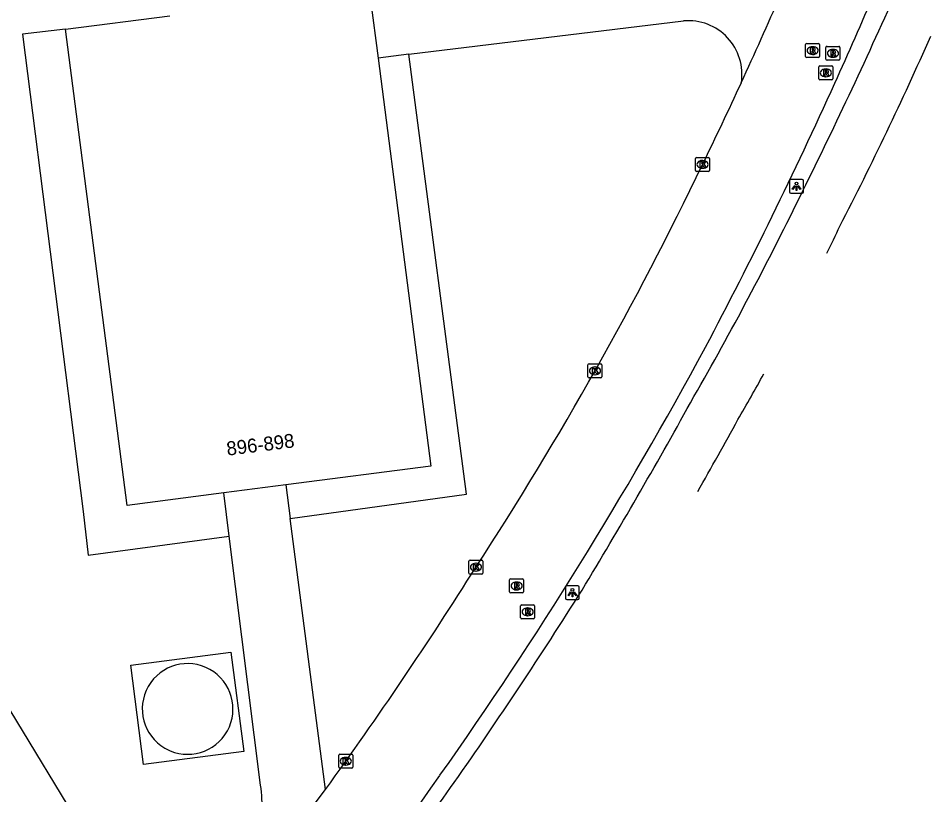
# Model space of a CAD drawing. Extents: x 154324 to 155743, y 382939 to 384183.
# Drawn here: x 155622.5 to 155688.2, y 383657.6 to 383713.4 of the extents above; entities that cross this region are included whole.
import ezdxf

# ---------------------------------------------------------------- set-up
doc = ezdxf.new("R2010")
doc.units = 0
for name, color, linetype in [('IMGEO_Fietspad_gesloten', 7, 'Continuous'), ('IMGEO_Kolk', 7, 'Continuous'), ('IMGEO_Lichtpunt', 7, 'Continuous'), ('IMGEO_Loofbos', 7, 'Continuous'), ('IMGEO_Opslagtank', 7, 'Continuous'), ('IMGEO_Pand', 7, 'Continuous'), ('IMGEO_Pand_nummerreeks', 7, 'Continuous'), ('IMGEO_Rijbaan_lokaal_gesloten', 7, 'Continuous'), ('IMGEO_Rijbaan_lokaal_open', 7, 'Continuous'), ('IMGEO_Rioolput', 7, 'Continuous'), ('IMGEO_Voetpad_gesloten', 7, 'Continuous'), ('IMGEO_Voetpad_open', 7, 'Continuous')]:
    doc.layers.add(name, color=color, linetype=linetype)

msp = doc.modelspace()

# ---------------------------------------------------------------- linework, layer by layer
at = {"layer": 'IMGEO_Fietspad_gesloten'}
for centre, radius, start, end in [((155322.907, 383877.011), 397.2, 333.53674, 335.8978), ((155458.585, 383813.415), 250.935, 332.72542, 336.18528), ((155452.6, 383811.231), 251.785, 330.10335, 333.78543), ((155506.608, 383781.846), 193.88, 333.87848, 334.51454), ((155506.608, 383781.846), 193.88, 329.86987, 330.98464), ((155318.174, 383880.881), 403.093, 328.83338, 331.04455), ((155440.078, 383812.046), 266.679, 330.15924, 331.43334), ((155375.44, 383853.45), 339.952, 324.99586, 327.79438), ((155331.975, 383886.464), 394.498, 322.54614, 324.68943)]:
    msp.add_arc(centre, radius, start, end, dxfattribs=at)
at = {"layer": 'IMGEO_Kolk'}
for p, q in [((155671.322, 383703.362), (155672.174, 383703.362)), ((155671.247, 383702.436), (155671.247, 383703.288)), ((155671.735, 383703.142), (155671.76, 383703.142)), ((155672.248, 383703.288), (155672.248, 383702.436)), ((155672.174, 383702.362), (155671.322, 383702.362)), ((155671.758, 383702.582), (155671.733, 383702.582)), ((155663.509, 383687.597), (155663.509, 383688.449)), ((155663.584, 383688.523), (155664.436, 383688.523)), ((155663.997, 383688.303), (155664.022, 383688.303)), ((155664.51, 383688.449), (155664.51, 383687.597)), ((155664.02, 383687.743), (155663.995, 383687.743)), ((155664.436, 383687.523), (155663.584, 383687.523)), ((155654.951, 383673.488), (155654.951, 383674.34)), ((155655.026, 383674.414), (155655.878, 383674.414)), ((155655.439, 383674.194), (155655.464, 383674.194)), ((155655.952, 383674.34), (155655.952, 383673.488)), ((155655.878, 383673.414), (155655.026, 383673.414)), ((155655.462, 383673.634), (155655.437, 383673.634)), ((155645.593, 383659.536), (155645.593, 383660.388)), ((155645.668, 383660.462), (155646.52, 383660.462)), ((155646.081, 383660.242), (155646.106, 383660.242)), ((155646.594, 383660.388), (155646.594, 383659.536)), ((155646.52, 383659.462), (155645.668, 383659.462)), ((155646.104, 383659.682), (155646.079, 383659.682))]:
    msp.add_line(p, q, dxfattribs=at)
for points in [[(155671.322, 383703.362), (155672.174, 383703.362)], [(155671.247, 383702.436), (155671.247, 383703.288)], [(155671.568, 383703.062), (155671.691, 383703.062), (155671.691, 383702.911), (155671.821, 383703.062), (155671.985, 383703.062), (155671.839, 383702.911), (155671.992, 383702.662), (155671.84, 383702.662), (155671.755, 383702.826), (155671.691, 383702.759), (155671.691, 383702.662), (155671.568, 383702.662), (155671.568, 383703.062)], [(155672.248, 383703.288), (155672.248, 383702.436)], [(155672.174, 383702.362), (155671.322, 383702.362)], [(155663.509, 383687.597), (155663.509, 383688.449)], [(155663.584, 383688.523), (155664.436, 383688.523)], [(155664.51, 383688.449), (155664.51, 383687.597)], [(155663.83, 383688.223), (155663.953, 383688.223), (155663.953, 383688.072), (155664.083, 383688.223), (155664.247, 383688.223), (155664.101, 383688.072), (155664.254, 383687.823), (155664.102, 383687.823), (155664.017, 383687.987), (155663.953, 383687.92), (155663.953, 383687.823), (155663.83, 383687.823), (155663.83, 383688.223)], [(155664.436, 383687.523), (155663.584, 383687.523)], [(155654.951, 383673.488), (155654.951, 383674.34)], [(155655.026, 383674.414), (155655.878, 383674.414)], [(155655.272, 383674.114), (155655.395, 383674.114), (155655.395, 383673.963), (155655.525, 383674.114), (155655.689, 383674.114), (155655.543, 383673.963), (155655.696, 383673.714), (155655.544, 383673.714), (155655.459, 383673.878), (155655.395, 383673.811), (155655.395, 383673.714), (155655.272, 383673.714), (155655.272, 383674.114)], [(155655.952, 383674.34), (155655.952, 383673.488)], [(155655.878, 383673.414), (155655.026, 383673.414)], [(155645.593, 383659.536), (155645.593, 383660.388)], [(155645.668, 383660.462), (155646.52, 383660.462)], [(155645.914, 383660.162), (155646.037, 383660.162), (155646.037, 383660.011), (155646.167, 383660.162), (155646.331, 383660.162), (155646.185, 383660.011), (155646.338, 383659.762), (155646.186, 383659.762), (155646.101, 383659.926), (155646.037, 383659.859), (155646.037, 383659.762), (155645.914, 383659.762), (155645.914, 383660.162)], [(155646.594, 383660.388), (155646.594, 383659.536)], [(155646.52, 383659.462), (155645.668, 383659.462)]]:
    msp.add_lwpolyline(points, dxfattribs=at)
for centre, start, end in [((155671.324, 383703.286), 91.55205, 178.44795), ((155671.324, 383703.286), 91.55205, 178.44795), ((155672.172, 383703.286), 1.55205, 88.44795), ((155672.172, 383703.286), 1.55205, 88.44795), ((155671.324, 383702.438), 181.55205, 268.44795), ((155671.324, 383702.438), 181.55205, 268.44795), ((155672.172, 383702.438), 271.55205, 358.44795), ((155672.172, 383702.438), 271.55205, 358.44795), ((155663.586, 383688.447), 91.55205, 178.44795), ((155663.586, 383688.447), 91.55205, 178.44795), ((155664.434, 383688.447), 1.55205, 88.44795), ((155664.434, 383688.447), 1.55205, 88.44795), ((155663.586, 383687.599), 181.55205, 268.44795), ((155663.586, 383687.599), 181.55205, 268.44795), ((155664.434, 383687.599), 271.55205, 358.44795), ((155664.434, 383687.599), 271.55205, 358.44795), ((155655.028, 383674.338), 91.55205, 178.44795), ((155655.028, 383674.338), 91.55205, 178.44795), ((155655.876, 383674.338), 1.55205, 88.44795), ((155655.876, 383674.338), 1.55205, 88.44795), ((155655.028, 383673.49), 181.55205, 268.44795), ((155655.028, 383673.49), 181.55205, 268.44795), ((155655.876, 383673.49), 271.55205, 358.44795), ((155655.876, 383673.49), 271.55205, 358.44795), ((155645.67, 383660.386), 91.55205, 178.44795), ((155645.67, 383660.386), 91.55205, 178.44795), ((155646.518, 383660.386), 1.55205, 88.44795), ((155646.518, 383660.386), 1.55205, 88.44795), ((155645.67, 383659.538), 181.55205, 268.44795), ((155645.67, 383659.538), 181.55205, 268.44795), ((155646.518, 383659.538), 271.55205, 358.44795), ((155646.518, 383659.538), 271.55205, 358.44795)]:
    msp.add_arc(centre, 0.0765, start, end, dxfattribs=at)
for centre, major_axis, ratio, start_param, end_param in [((155671.734, 383702.862), (-0.387, 0.002), 0.722429, 4.712389, 7.853982), ((155671.759, 383702.862), (-0.39, 0.002), 0.717154, 1.570796, 4.712389), ((155663.996, 383688.023), (-0.387, 0.002), 0.722429, 4.712389, 7.853982), ((155664.021, 383688.023), (-0.39, 0.002), 0.717154, 1.570796, 4.712389), ((155655.438, 383673.914), (-0.387, 0.002), 0.722429, 4.712389, 7.853982), ((155655.463, 383673.914), (-0.39, 0.002), 0.717154, 1.570796, 4.712389), ((155646.08, 383659.962), (-0.387, 0.002), 0.722429, 4.712389, 7.853982), ((155646.105, 383659.962), (-0.39, 0.002), 0.717154, 1.570796, 4.712389)]:
    msp.add_ellipse(centre, major_axis=major_axis, ratio=ratio, start_param=start_param, end_param=end_param, dxfattribs=at)
at = {"layer": 'IMGEO_Lichtpunt'}
for p, q in [((155678.005, 383701.689), (155678.005, 383700.882)), ((155678.005, 383701.689), (155678.005, 383700.882)), ((155678.907, 383701.784), (155678.099, 383701.784)), ((155678.907, 383701.784), (155678.099, 383701.784)), ((155679.001, 383700.882), (155679.001, 383701.689)), ((155679.001, 383700.882), (155679.001, 383701.689)), ((155678.099, 383700.788), (155678.907, 383700.788)), ((155678.099, 383700.788), (155678.907, 383700.788)), ((155662.788, 383672.581), (155661.98, 383672.581)), ((155662.788, 383672.581), (155661.98, 383672.581)), ((155661.886, 383672.486), (155661.886, 383671.679)), ((155661.886, 383672.486), (155661.886, 383671.679)), ((155662.882, 383671.679), (155662.882, 383672.486)), ((155662.882, 383671.679), (155662.882, 383672.486)), ((155661.98, 383671.585), (155662.788, 383671.585)), ((155661.98, 383671.585), (155662.788, 383671.585))]:
    msp.add_line(p, q, dxfattribs=at)
for points in [[(155678.379, 383701.353), (155678.418, 383701.325), (155678.23, 383701.063), (155678.192, 383701.09), (155678.379, 383701.353)], [(155678.481, 383701.305), (155678.528, 383701.305), (155678.528, 383700.983), (155678.481, 383700.983), (155678.481, 383701.305)], [(155678.591, 383701.325), (155678.629, 383701.352), (155678.816, 383701.09), (155678.777, 383701.062), (155678.591, 383701.325)], [(155662.26, 383672.15), (155662.299, 383672.122), (155662.111, 383671.86), (155662.073, 383671.887), (155662.26, 383672.15)], [(155662.362, 383672.102), (155662.409, 383672.102), (155662.409, 383671.78), (155662.362, 383671.78), (155662.362, 383672.102)], [(155662.472, 383672.122), (155662.51, 383672.149), (155662.697, 383671.887), (155662.658, 383671.859), (155662.472, 383672.122)]]:
    msp.add_lwpolyline(points, dxfattribs=at)
for centre in [(155678.504, 383701.487), (155662.385, 383672.284)]:
    msp.add_circle(centre, 0.0994, dxfattribs=at)
for centre, start, end in [((155678.099, 383701.689), 90, 180), ((155678.099, 383701.689), 90, 180), ((155678.907, 383701.689), 0, 90), ((155678.907, 383701.689), 0, 90), ((155678.099, 383700.882), 180, 270), ((155678.099, 383700.882), 180, 270), ((155678.907, 383700.882), 270, 0), ((155678.907, 383700.882), 270, 360), ((155661.98, 383672.486), 90, 180), ((155661.98, 383672.486), 90, 180), ((155662.788, 383672.486), 0, 90), ((155662.788, 383672.486), 0, 90), ((155661.98, 383671.679), 180, 270), ((155661.98, 383671.679), 180, 270), ((155662.788, 383671.679), 270, 0), ((155662.788, 383671.679), 270, 360)]:
    msp.add_arc(centre, 0.0946, start, end, dxfattribs=at)
at = {"layer": 'IMGEO_Loofbos'}
msp.add_lwpolyline([(155588.986, 383764.634), (155584.778, 383742.905), (155608.878, 383712.126), (155621.944, 383663.636), (155632.059, 383646.947)], dxfattribs=at)
at = {"layer": 'IMGEO_Opslagtank'}
msp.add_lwpolyline([(155633.081, 383660.904), (155633.17, 383660.854)], dxfattribs=at)
msp.add_arc((155634.722, 383663.721), 3.26, 241.5698, 239.77584, dxfattribs=at)
at = {"layer": 'IMGEO_Pand'}
for points in [[(155647.881, 383714.683), (155648.42, 383710.507)], [(155625.95, 383712.576), (155633.448, 383713.544)], [(155637.322, 383679.252), (155630.369, 383678.354), (155625.95, 383712.576)], [(155648.42, 383710.507), (155652.207, 383681.174), (155641.773, 383679.827)], [(155641.773, 383679.827), (155637.322, 383679.252)]]:
    msp.add_lwpolyline(points, dxfattribs=at)
at = {"layer": 'IMGEO_Rijbaan_lokaal_gesloten'}
msp.add_lwpolyline([(155637.795, 383648.897), (155644.632, 383657.932)], dxfattribs=at)
for centre, radius, start, end in [((155351.213, 383857.223), 355.788, 335.33276, 337.55941), ((155377.377, 383846.123), 333.511, 335.66773, 336.89215), ((155392.408, 383838.997), 310.747, 334.01796, 335.21676), ((155372.273, 383848.441), 339.117, 332.0934, 335.66608), ((155439.555, 383814.512), 257.642, 326.92673, 334.31943), ((155406.035, 383833.355), 302.23, 324.75564, 331.62534), ((155410.012, 383828.426), 290.025, 323.99477, 327.80831), ((155441.275, 383805.327), 257.289, 317.26147, 325.32443)]:
    msp.add_arc(centre, radius, start, end, dxfattribs=at)
at = {"layer": 'IMGEO_Rijbaan_lokaal_open'}
for points in [[(155650.638, 383710.777), (155670.387, 383713.18)], [(155650.638, 383710.777), (155648.42, 383710.507)], [(155641.773, 383679.827), (155642.087, 383677.42)], [(155637.712, 383676.149), (155637.322, 383679.252)], [(155644.632, 383657.932), (155642.087, 383677.42)], [(155639.962, 383658.245), (155637.712, 383676.149)]]:
    msp.add_lwpolyline(points, dxfattribs=at)
for centre, radius, start, end in [((155670.721, 383709.333), 3.861, 351.09807, 94.95574), ((155630.953, 383656.773), 9.128, 344.27941, 9.27889)]:
    msp.add_arc(centre, radius, start, end, dxfattribs=at)
at = {"layer": 'IMGEO_Rioolput'}
for p, q in [((155679.159, 383710.62), (155679.159, 383711.472)), ((155679.234, 383711.546), (155680.086, 383711.546)), ((155679.647, 383711.326), (155679.672, 383711.326)), ((155680.16, 383711.472), (155680.16, 383710.62)), ((155680.622, 383710.423), (155680.622, 383711.275)), ((155680.697, 383711.349), (155681.549, 383711.349)), ((155681.623, 383711.275), (155681.623, 383710.423)), ((155679.67, 383710.766), (155679.645, 383710.766)), ((155681.133, 383710.569), (155681.108, 383710.569)), ((155681.11, 383711.129), (155681.135, 383711.129)), ((155680.086, 383710.546), (155679.234, 383710.546)), ((155680.187, 383709.942), (155681.039, 383709.942)), ((155681.549, 383710.349), (155680.697, 383710.349)), ((155680.112, 383709.016), (155680.112, 383709.868)), ((155680.6, 383709.722), (155680.625, 383709.722)), ((155681.113, 383709.868), (155681.113, 383709.016)), ((155681.039, 383708.942), (155680.187, 383708.942)), ((155680.623, 383709.162), (155680.598, 383709.162)), ((155657.876, 383672.138), (155657.876, 383672.99)), ((155657.951, 383673.064), (155658.803, 383673.064)), ((155658.364, 383672.844), (155658.389, 383672.844)), ((155658.877, 383672.99), (155658.877, 383672.138)), ((155658.803, 383672.064), (155657.951, 383672.064)), ((155658.387, 383672.284), (155658.362, 383672.284)), ((155658.743, 383671.201), (155659.595, 383671.201)), ((155658.668, 383670.275), (155658.668, 383671.127)), ((155659.156, 383670.981), (155659.181, 383670.981)), ((155659.669, 383671.127), (155659.669, 383670.275)), ((155659.595, 383670.201), (155658.743, 383670.201)), ((155659.179, 383670.421), (155659.154, 383670.421))]:
    msp.add_line(p, q, dxfattribs=at)
for points in [[(155679.159, 383710.62), (155679.159, 383711.472)], [(155679.234, 383711.546), (155680.086, 383711.546)], [(155679.748, 383711.244), (155679.496, 383711.246), (155679.496, 383710.846)], [(155680.16, 383711.472), (155680.16, 383710.62)], [(155680.622, 383710.423), (155680.622, 383711.275)], [(155680.697, 383711.349), (155681.549, 383711.349)], [(155681.623, 383711.275), (155681.623, 383710.423)], [(155679.496, 383710.846), (155679.62, 383710.846), (155679.62, 383711.008), (155679.631, 383711.008)], [(155679.674, 383711.165), (155679.62, 383711.165), (155679.62, 383711.084)], [(155679.62, 383711.084), (155679.672, 383711.084)], [(155679.678, 383710.979), (155679.749, 383710.846), (155679.889, 383710.846), (155679.824, 383710.972)], [(155681.211, 383711.047), (155680.959, 383711.049), (155680.959, 383710.649)], [(155680.959, 383710.649), (155681.083, 383710.649), (155681.083, 383710.811), (155681.094, 383710.811)], [(155681.137, 383710.968), (155681.083, 383710.968), (155681.083, 383710.887)], [(155681.083, 383710.887), (155681.135, 383710.887)], [(155681.141, 383710.782), (155681.212, 383710.649), (155681.352, 383710.649), (155681.287, 383710.775)], [(155680.086, 383710.546), (155679.234, 383710.546)], [(155680.187, 383709.942), (155681.039, 383709.942)], [(155681.549, 383710.349), (155680.697, 383710.349)], [(155680.112, 383709.016), (155680.112, 383709.868)], [(155680.701, 383709.64), (155680.449, 383709.642), (155680.449, 383709.242)], [(155680.449, 383709.242), (155680.573, 383709.242), (155680.573, 383709.404), (155680.584, 383709.404)], [(155680.627, 383709.561), (155680.573, 383709.561), (155680.573, 383709.48)], [(155680.573, 383709.48), (155680.625, 383709.48)], [(155680.631, 383709.375), (155680.702, 383709.242), (155680.842, 383709.242), (155680.777, 383709.368)], [(155681.113, 383709.868), (155681.113, 383709.016)], [(155681.039, 383708.942), (155680.187, 383708.942)], [(155657.876, 383672.138), (155657.876, 383672.99)], [(155657.951, 383673.064), (155658.803, 383673.064)], [(155658.465, 383672.762), (155658.213, 383672.764), (155658.213, 383672.364)], [(155658.213, 383672.364), (155658.337, 383672.364), (155658.337, 383672.526), (155658.348, 383672.526)], [(155658.391, 383672.683), (155658.337, 383672.683), (155658.337, 383672.602)], [(155658.337, 383672.602), (155658.389, 383672.602)], [(155658.877, 383672.99), (155658.877, 383672.138)], [(155658.803, 383672.064), (155657.951, 383672.064)], [(155658.395, 383672.497), (155658.466, 383672.364), (155658.606, 383672.364), (155658.541, 383672.49)], [(155658.743, 383671.201), (155659.595, 383671.201)], [(155658.668, 383670.275), (155658.668, 383671.127)], [(155659.257, 383670.899), (155659.005, 383670.901), (155659.005, 383670.501)], [(155659.005, 383670.501), (155659.129, 383670.501), (155659.129, 383670.663), (155659.14, 383670.663)], [(155659.183, 383670.82), (155659.129, 383670.82), (155659.129, 383670.739)], [(155659.129, 383670.739), (155659.181, 383670.739)], [(155659.187, 383670.634), (155659.258, 383670.501), (155659.398, 383670.501), (155659.333, 383670.627)], [(155659.669, 383671.127), (155659.669, 383670.275)], [(155659.595, 383670.201), (155658.743, 383670.201)]]:
    msp.add_lwpolyline(points, dxfattribs=at)
for centre, radius, start, end in [((155679.236, 383711.47), 0.0765, 91.55205, 178.44795), ((155679.236, 383711.47), 0.0765, 91.55205, 178.44795), ((155679.747, 383711.134), 0.109, 350.36119, 89.41601), ((155680.084, 383711.47), 0.0765, 1.55205, 88.44795), ((155680.084, 383711.47), 0.0765, 1.55205, 88.44795), ((155680.699, 383711.273), 0.0765, 91.55205, 178.44795), ((155680.699, 383711.273), 0.0765, 91.55205, 178.44795), ((155681.547, 383711.273), 0.0765, 1.55205, 88.44795), ((155681.547, 383711.273), 0.0765, 1.55205, 88.44795), ((155679.236, 383710.622), 0.0765, 181.55205, 268.44795), ((155679.236, 383710.622), 0.0765, 181.55205, 268.44795), ((155679.63, 383710.955), 0.0533, 26.02933, 88.69889), ((155679.656, 383711.273), 0.19, 274.7715, 282.96867), ((155679.68, 383711.069), 0.0964, 77.00612, 93.18647), ((155679.694, 383711.126), 0.0378, 276.66336, 79.67722), ((155679.745, 383711.134), 0.112, 277.58423, 350.98172), ((155679.729, 383710.919), 0.108, 29.51342, 73.79051), ((155680.084, 383710.622), 0.0765, 271.55205, 358.44795), ((155680.084, 383710.622), 0.0765, 271.55205, 358.44795), ((155681.093, 383710.758), 0.0533, 26.02933, 88.69889), ((155681.119, 383711.076), 0.19, 274.7715, 282.96867), ((155681.143, 383710.872), 0.0964, 77.00612, 93.18647), ((155681.157, 383710.929), 0.0378, 276.66336, 79.67722), ((155681.21, 383710.937), 0.109, 350.36119, 89.41601), ((155681.208, 383710.937), 0.112, 277.58423, 350.98172), ((155681.192, 383710.722), 0.108, 29.51342, 73.79051), ((155680.189, 383709.866), 0.0765, 91.55205, 178.44795), ((155680.189, 383709.866), 0.0765, 91.55205, 178.44795), ((155680.699, 383710.425), 0.0765, 181.55205, 268.44795), ((155680.699, 383710.425), 0.0765, 181.55205, 268.44795), ((155681.037, 383709.866), 0.0765, 1.55205, 88.44795), ((155681.037, 383709.866), 0.0765, 1.55205, 88.44795), ((155681.547, 383710.425), 0.0765, 271.55205, 358.44795), ((155681.547, 383710.425), 0.0765, 271.55205, 358.44795), ((155680.583, 383709.351), 0.0533, 26.02933, 88.69889), ((155680.609, 383709.669), 0.19, 274.7715, 282.96867), ((155680.633, 383709.465), 0.0964, 77.00612, 93.18647), ((155680.647, 383709.522), 0.0378, 276.66336, 79.67722), ((155680.7, 383709.53), 0.109, 350.36119, 89.41601), ((155680.698, 383709.53), 0.112, 277.58423, 350.98172), ((155680.682, 383709.315), 0.108, 29.51342, 73.79051), ((155680.189, 383709.018), 0.0765, 181.55205, 268.44795), ((155680.189, 383709.018), 0.0765, 181.55205, 268.44795), ((155681.037, 383709.018), 0.0765, 271.55205, 358.44795), ((155681.037, 383709.018), 0.0765, 271.55205, 358.44795), ((155657.953, 383672.988), 0.0765, 91.55205, 178.44795), ((155657.953, 383672.988), 0.0765, 91.55205, 178.44795), ((155658.347, 383672.473), 0.0533, 26.02933, 88.69889), ((155658.373, 383672.791), 0.19, 274.7715, 282.96867), ((155658.397, 383672.587), 0.0964, 77.00612, 93.18647), ((155658.411, 383672.644), 0.0378, 276.66336, 79.67722), ((155658.464, 383672.652), 0.109, 350.36119, 89.41601), ((155658.462, 383672.652), 0.112, 277.58423, 350.98172), ((155658.446, 383672.437), 0.108, 29.51342, 73.79051), ((155658.801, 383672.988), 0.0765, 1.55205, 88.44795), ((155658.801, 383672.988), 0.0765, 1.55205, 88.44795), ((155657.953, 383672.14), 0.0765, 181.55205, 268.44795), ((155657.953, 383672.14), 0.0765, 181.55205, 268.44795), ((155658.801, 383672.14), 0.0765, 271.55205, 358.44795), ((155658.801, 383672.14), 0.0765, 271.55205, 358.44795), ((155658.745, 383671.125), 0.0765, 91.55205, 178.44795), ((155658.745, 383671.125), 0.0765, 91.55205, 178.44795), ((155659.593, 383671.125), 0.0765, 1.55205, 88.44795), ((155659.593, 383671.125), 0.0765, 1.55205, 88.44795), ((155659.139, 383670.61), 0.0533, 26.02933, 88.69889), ((155659.165, 383670.928), 0.19, 274.7715, 282.96867), ((155659.189, 383670.724), 0.0964, 77.00612, 93.18647), ((155659.203, 383670.781), 0.0378, 276.66336, 79.67722), ((155659.256, 383670.789), 0.109, 350.36119, 89.41601), ((155659.254, 383670.789), 0.112, 277.58423, 350.98172), ((155659.238, 383670.574), 0.108, 29.51342, 73.79051), ((155658.745, 383670.277), 0.0765, 181.55205, 268.44795), ((155658.745, 383670.277), 0.0765, 181.55205, 268.44795), ((155659.593, 383670.277), 0.0765, 271.55205, 358.44795), ((155659.593, 383670.277), 0.0765, 271.55205, 358.44795)]:
    msp.add_arc(centre, radius, start, end, dxfattribs=at)
for centre, major_axis, ratio, start_param, end_param in [((155679.646, 383711.046), (-0.387, 0.002), 0.722429, 4.712389, 7.853982), ((155679.671, 383711.046), (-0.39, 0.002), 0.717154, 1.570796, 4.712389), ((155681.109, 383710.849), (-0.387, 0.002), 0.722429, 4.712389, 7.853982), ((155681.134, 383710.849), (-0.39, 0.002), 0.717154, 1.570796, 4.712389), ((155680.599, 383709.442), (-0.387, 0.002), 0.722429, 4.712389, 7.853982), ((155680.624, 383709.442), (-0.39, 0.002), 0.717154, 1.570796, 4.712389), ((155658.363, 383672.564), (-0.387, 0.002), 0.722429, 4.712389, 7.853982), ((155658.388, 383672.564), (-0.39, 0.002), 0.717154, 1.570796, 4.712389), ((155659.155, 383670.701), (-0.387, 0.002), 0.722429, 4.712389, 7.853982), ((155659.18, 383670.701), (-0.39, 0.002), 0.717154, 1.570796, 4.712389)]:
    msp.add_ellipse(centre, major_axis=major_axis, ratio=ratio, start_param=start_param, end_param=end_param, dxfattribs=at)
at = {"layer": 'IMGEO_Voetpad_gesloten'}
msp.add_lwpolyline([(155637.832, 383667.806), (155638.755, 383660.655), (155631.559, 383659.726), (155630.636, 383666.878), (155637.832, 383667.806)], dxfattribs=at)
at = {"layer": 'IMGEO_Voetpad_open'}
for points in [[(155625.95, 383712.576), (155622.843, 383712.235), (155627.219, 383677.909), (155627.569, 383674.769), (155637.712, 383676.149)], [(155642.087, 383677.42), (155654.779, 383679.151), (155650.638, 383710.777)]]:
    msp.add_lwpolyline(points, dxfattribs=at)

# ---------------------------------------------------------------- texts
at = {"layer": 'IMGEO_Pand_nummerreeks'}
msp.add_text('896-898', height=1, rotation=7.12755, dxfattribs=at).set_placement((155637.579, 383681.925))

doc.saveas('drawing.dxf')
